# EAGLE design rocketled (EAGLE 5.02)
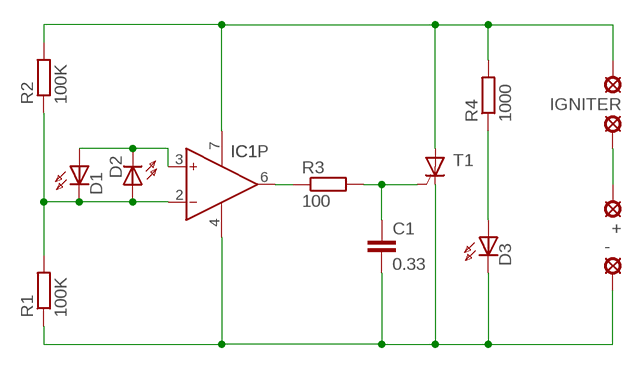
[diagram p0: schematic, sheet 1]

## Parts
+  SE11  [SE11]
-  SE11  [SE11]
.  SE11  [SE11]
C1  0.33  C-EUC0805K  [C0805K]
D1  HLMP6  [HLMP6]
D2  HLMP6  [HLMP6]
D3  HLMP6  [HLMP6]
IC1  AD811_SO8  [SO8]
IGNITER  SE11  [SE11]
R1  100K  R-EU_M0805  [M0805]
R2  100K  R-EU_M0805  [M0805]
R3  100  R-EU_M0805  [M0805]
R4  1000  R-EU_M0805  [M0805]
T1  BT151  [TO220CL]

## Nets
N$1: D1.K D2.A IC1.2(IN-) R1.2 R2.1
N$2: IC1.7(V+) IGNITER.MP R2.2 R4.2 T1.A
N$4: C1.1 R3.2 T1.G
N$5: D3.A R4.1
N$6: -.MP C1.2 D3.K IC1.4(V-) R1.1 T1.C
N$7: D1.A D2.K IC1.3(IN+)
N$8: +.MP ..MP
N$9: IC1.6(OUT) R3.1
Unconnected: IC1.1(NC) IC1.5(NC) IC1.8(NC)

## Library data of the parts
+ - . IGNITER = solpad:SE11: SOLDER PAD
C1 = rcl:C-EU: CAPACITOR, European symbol
D1-D3 = display-hp:HLMP6: LED
IC1 = analog-devices:AD811_SO8: ANALOG DEVICES
R1-R4 = rcl:R-EU_: RESISTOR, European symbol
T1 = triac:BT151: THYRISTOR

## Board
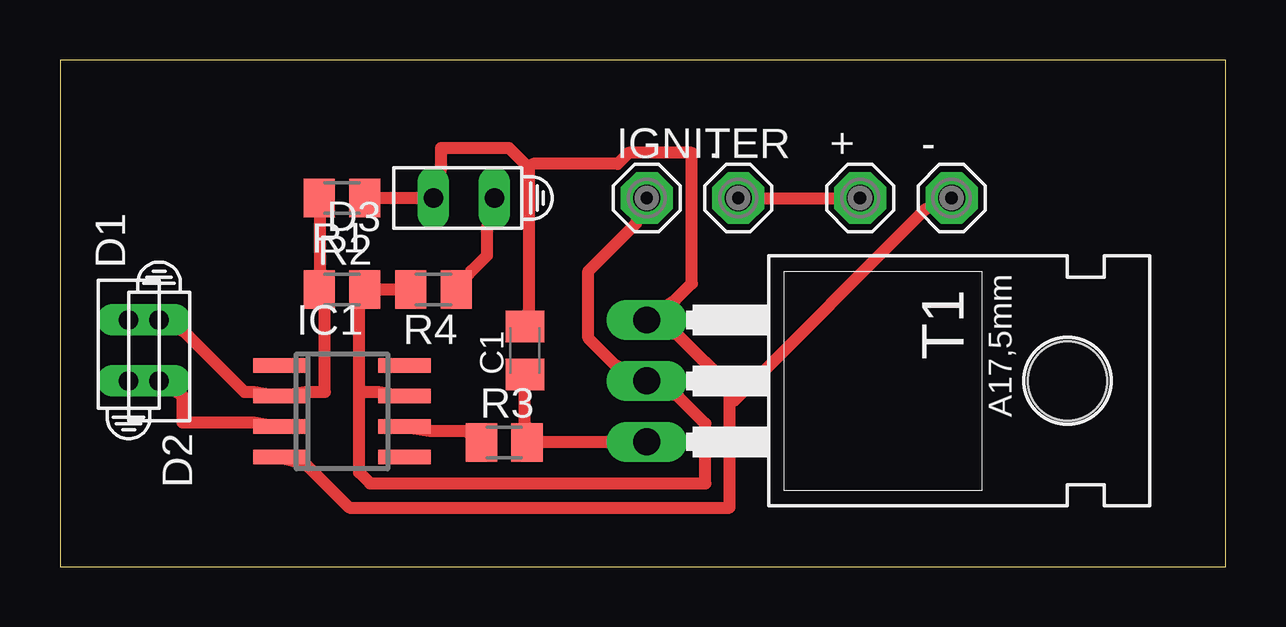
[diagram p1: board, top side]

Size 48.58 x 21.12 mm. Coordinates in mm from the lower left corner, seen from the top.
Outline: 0,0 48.58,0 48.58,21.12 0,21.12 0,0
Copper layers 1: Top 0.035mm
Design rules "default": minimum track width 20mil, minimum drill 20mil, track to track 20mil, track to pad 20mil, pad to pad 20mil, via to via 20mil, smd to smd 25mil, copper to edge 20mil, drill to drill 8mil, minimum pad ring 10mil, minimum via ring 8mil, stop-mask expansion 4mil, vias tented up to drill 0mil, thermal gap 10mil

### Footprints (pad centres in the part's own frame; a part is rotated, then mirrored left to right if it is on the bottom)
SE11 = drill 1.118 pad 2.159 octagon: MP 0,0
C0805K = smd 1.3 x 1.6: 1 -1,0; 2 1,0
HLMP6 = drill 0.813 long: A -1.27,0; K 1.27,0
SO8 = smd 0.6 x 2.2: 1 -1.905,-2.6; 2 -0.635,-2.6; 3 0.635,-2.6; 4 1.905,-2.6; 5 1.905,2.6; 6 0.635,2.6; 7 -0.635,2.6; 8 -1.905,2.6
M0805 = smd 1.3 x 1.6: 1 -0.95,0; 2 0.95,0
TO220CL = drill 1.118 long: A 0,-6.35; C -2.54,-6.35; G 2.54,-6.35 | hole 3.302: 0,11.176

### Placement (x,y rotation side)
+  33.34,15.37 0 top
-  37.15,15.37 0 top
.  28.26,15.37 0 top
C1  19.37,9.02 90 top
D1  2.86,9.02 90 top
D2  4.13,9.02 270 top
D3  16.83,15.37 180 top
IC1  11.75,6.48 270 top
IGNITER  24.45,15.37 0 top
R1  11.75,15.37 180 top
R2  11.75,11.56 0 top
R3  18.51,5.19 0 top
R4  15.56,11.56 180 top
T1  30.8,7.75 270 top

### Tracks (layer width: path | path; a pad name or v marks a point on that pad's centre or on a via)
N$1
  Top 0.508: D1.K D2.A 5.2,9.78 7.69,7.29 8.09,7.29 IC1.2 10.23,7.29 11.04,7.29 11.04,10.8 R2.1 10.84,12.32 10.84,14.61 R1.2
N$2
  Top 0.508: R4.2 R2.2 12.46,10.8 12.46,7.29 | 12.46,7.29 13.27,7.29 IC1.7 | IGNITER.MP 23.99,14.3 22.01,12.32 22.01,9.53 23.13,8.41 T1.A 25.77,7.09 26.89,5.97 26.89,3.48 12.92,3.48 12.46,3.94 12.46,7.29
N$4
  Top 0.508: C1.1 19.37,5.97 R3.2 20.08,5.21 T1.G
N$5
  Top 0.508: R4.1 17.13,12.32 17.8,12.98 17.8,14.1 D3.A
N$6
  Top 0.508: R1.1 D3.K 15.87,16.64 15.87,17.45 18.71,17.45 19.52,16.64 | 19.52,16.64 19.52,10.65 C1.2 | 27.9,6.94 27.9,7.5 25.77,9.63 T1.C 25.62,11.1 26.33,11.81 26.33,17.25 23.69,17.25 23.23,16.79 19.73,16.79 19.52,16.64 | 27.9,6.94 27.9,2.47 12.06,2.47 10.23,4.3 IC1.4 | -.MP 36.08,14.91 28.11,6.94 27.9,6.94
N$7
  Top 0.508: IC1.3 8.09,6.02 5.1,6.02 5.1,7.14 D2.K D1.A
N$8
  Top 0.508: ..MP +.MP
N$9
  Top 0.508: R3.1 16.93,5.67 15.41,5.67 IC1.6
